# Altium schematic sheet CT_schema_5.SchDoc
size 316 x 185 mm
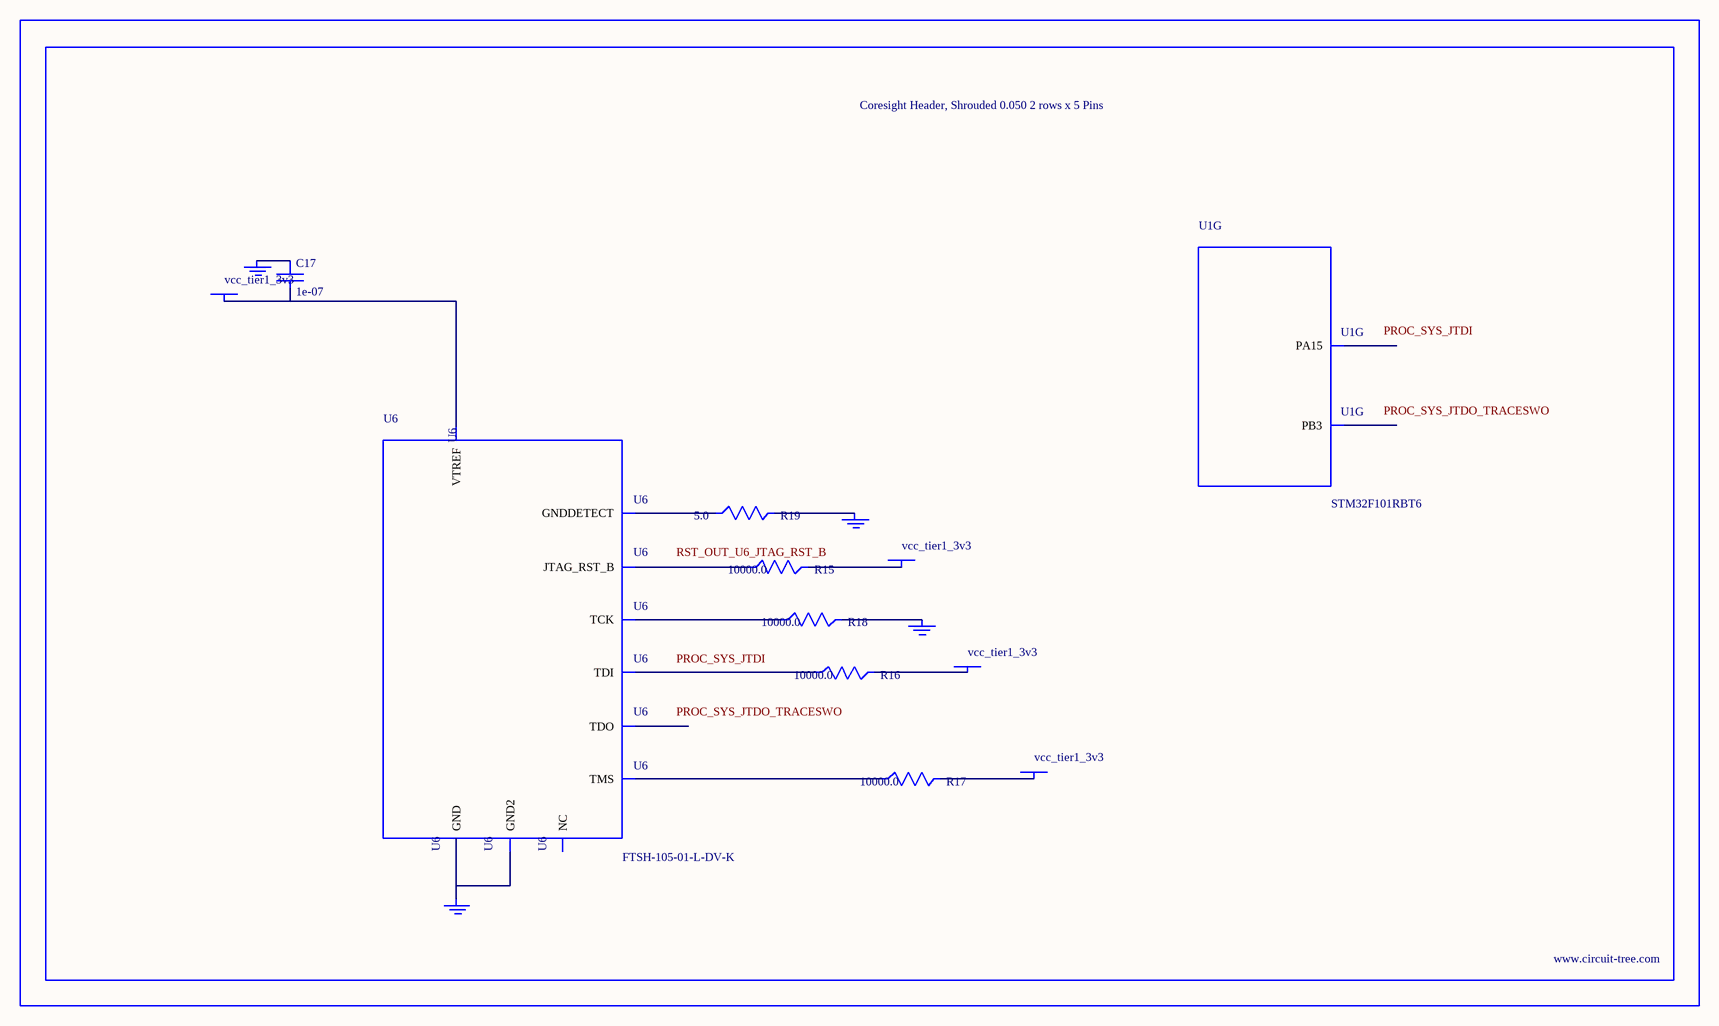
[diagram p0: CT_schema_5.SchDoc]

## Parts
BORDER4  (no value)
C17  1e-07  [C0402]
GND_INSTANCE_4_0  (no value)
GND_INSTANCE_4_1  (no value)
GND_INSTANCE_4_2  (no value)
GND_INSTANCE_4_3  (no value)
POWER_INSTANCE_4_0  vcc_tier1_3v3
POWER_INSTANCE_4_1  vcc_tier1_3v3
POWER_INSTANCE_4_2  vcc_tier1_3v3
POWER_INSTANCE_4_3  vcc_tier1_3v3
R15  10000.0  [R0603]
R16  10000.0  [R0603]
R17  10000.0  [R0603]
R18  10000.0  [R0603]
R19  5.0  [R0603]
U1  STM32F101RBT6  [LQFP64]  (part G of 7)
U6  FTSH-105-01-L-DV-K  [SAMTEC_FTSH-105-01-L-DV-K]

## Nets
NetC17_1: C17.1 GND_INSTANCE_4_0.0(GND)
NetC17_2: C17.2 POWER_INSTANCE_4_0.0(PWR) U6.1(VTREF)
NetGND_INSTANCE_4_1_0: GND_INSTANCE_4_1.0(GND) R18.2
NetGND_INSTANCE_4_2_0: GND_INSTANCE_4_2.0(GND) R19.2
NetGND_INSTANCE_4_3_0: GND_INSTANCE_4_3.0(GND) U6.3(GND) U6.5(GND2)
NetPOWER_INSTANCE_4_1_0: POWER_INSTANCE_4_1.0(PWR) R17.2
NetPOWER_INSTANCE_4_2_0: POWER_INSTANCE_4_2.0(PWR) R16.2
NetPOWER_INSTANCE_4_3_0: POWER_INSTANCE_4_3.0(PWR) R15.2
NetR15_1: R15.1 U6.10(JTAG_RST_B)
NetR16_1: R16.1 U6.8(TDI)
NetR17_1: R17.1 U6.2(TMS)
NetR18_1: R18.1 U6.4(TCK)
NetR19_1: R19.1 U6.9(GNDDETECT)

Not connected (* = marked no-connect by the designer): U1 50(PA15) 55(PB3); U6 6(TDO) 7(NC)

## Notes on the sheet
- Labels drawn without touching a wire or pin: PROC_SYS_JTDI, PROC_SYS_JTDO_TRACESWO, RST_OUT_U6_JTAG_RST_B

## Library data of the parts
BORDER4 = BORDER_PAGE4
C17 = C0402C104K3RACTU
GND_INSTANCE_4_0-GND_INSTANCE_4_3 = GND
POWER_INSTANCE_4_0-POWER_INSTANCE_4_3 = PWR
R15-R18 = RC0603JR-0710KL
R19 = ERJ-3GEYJ5R1V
